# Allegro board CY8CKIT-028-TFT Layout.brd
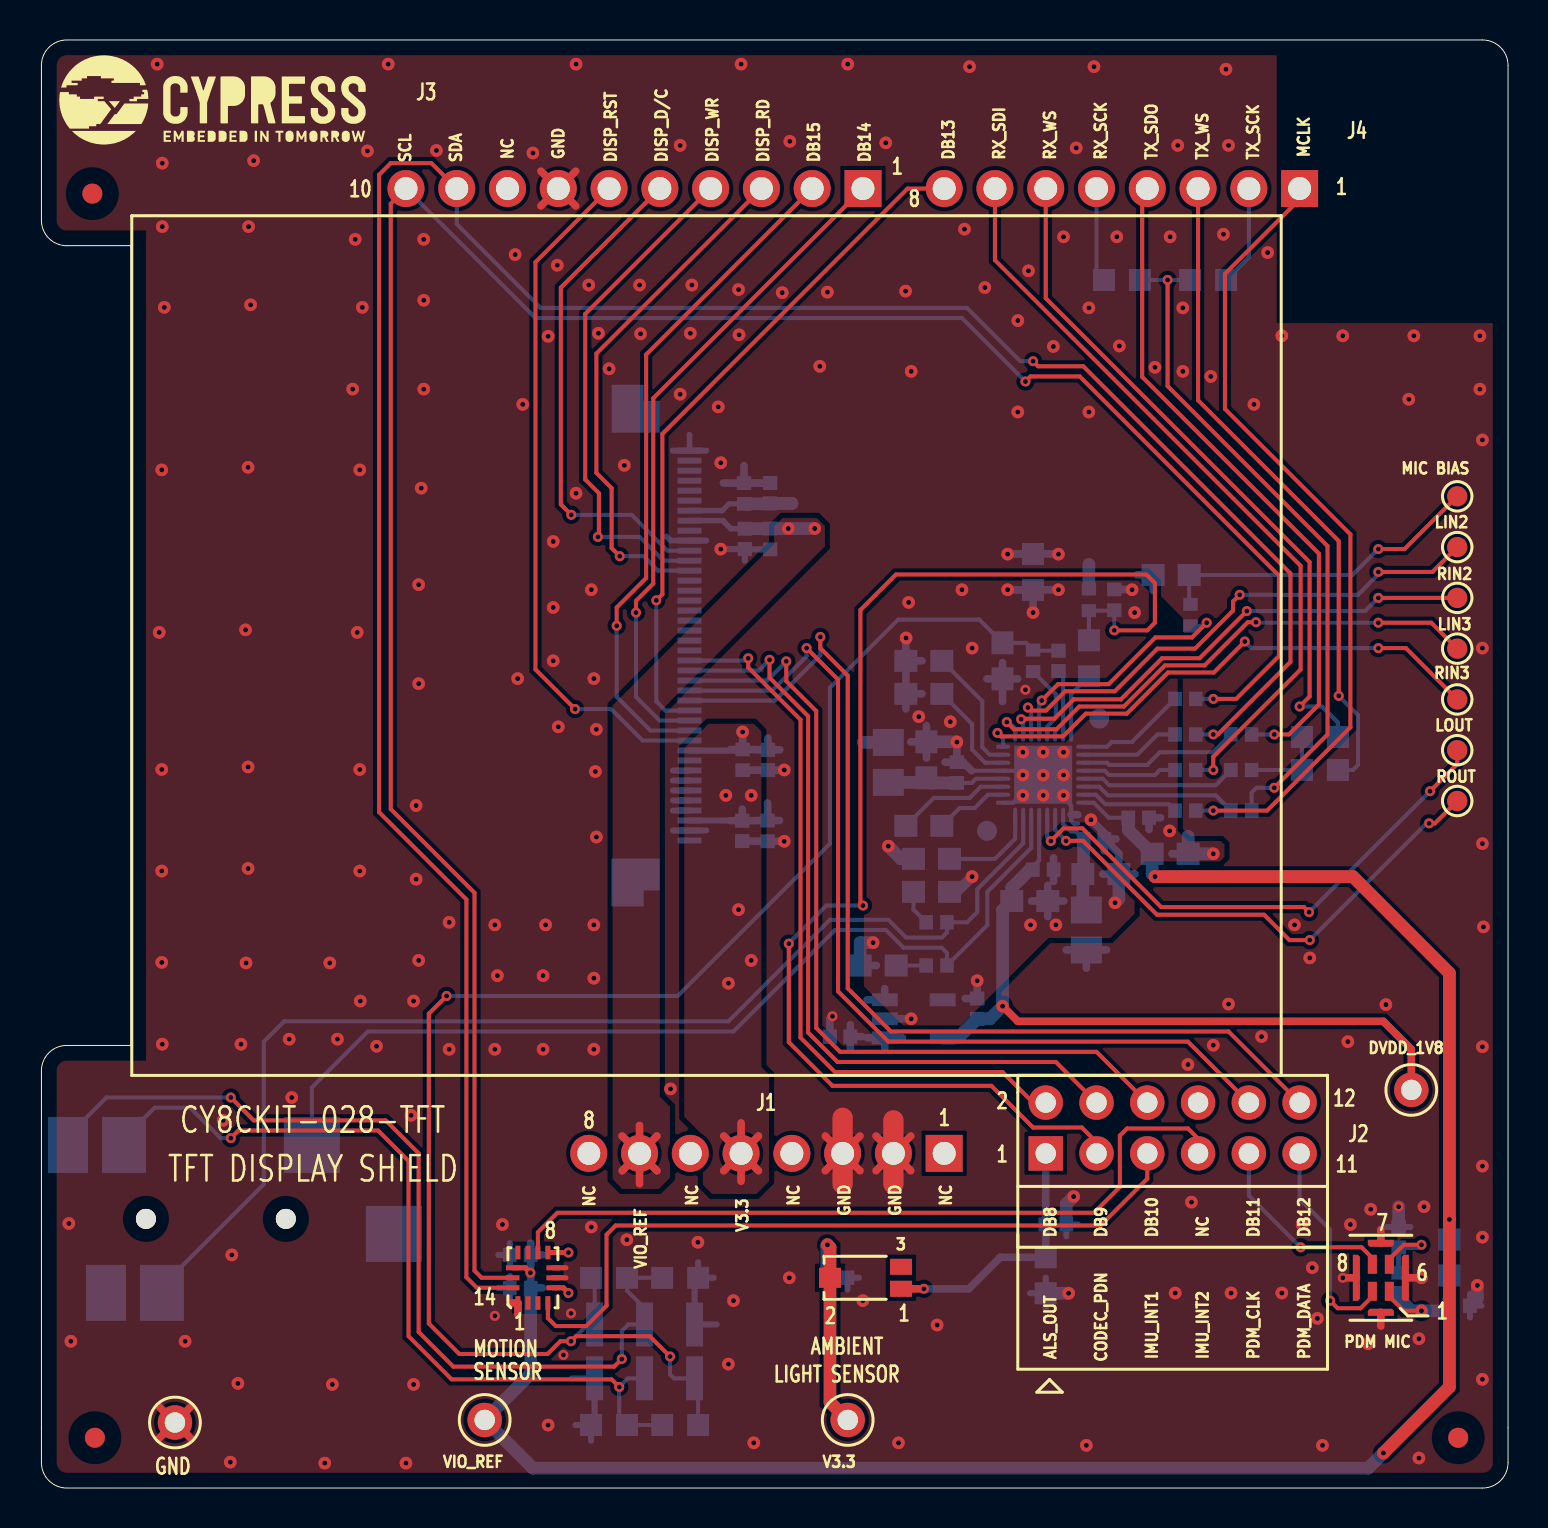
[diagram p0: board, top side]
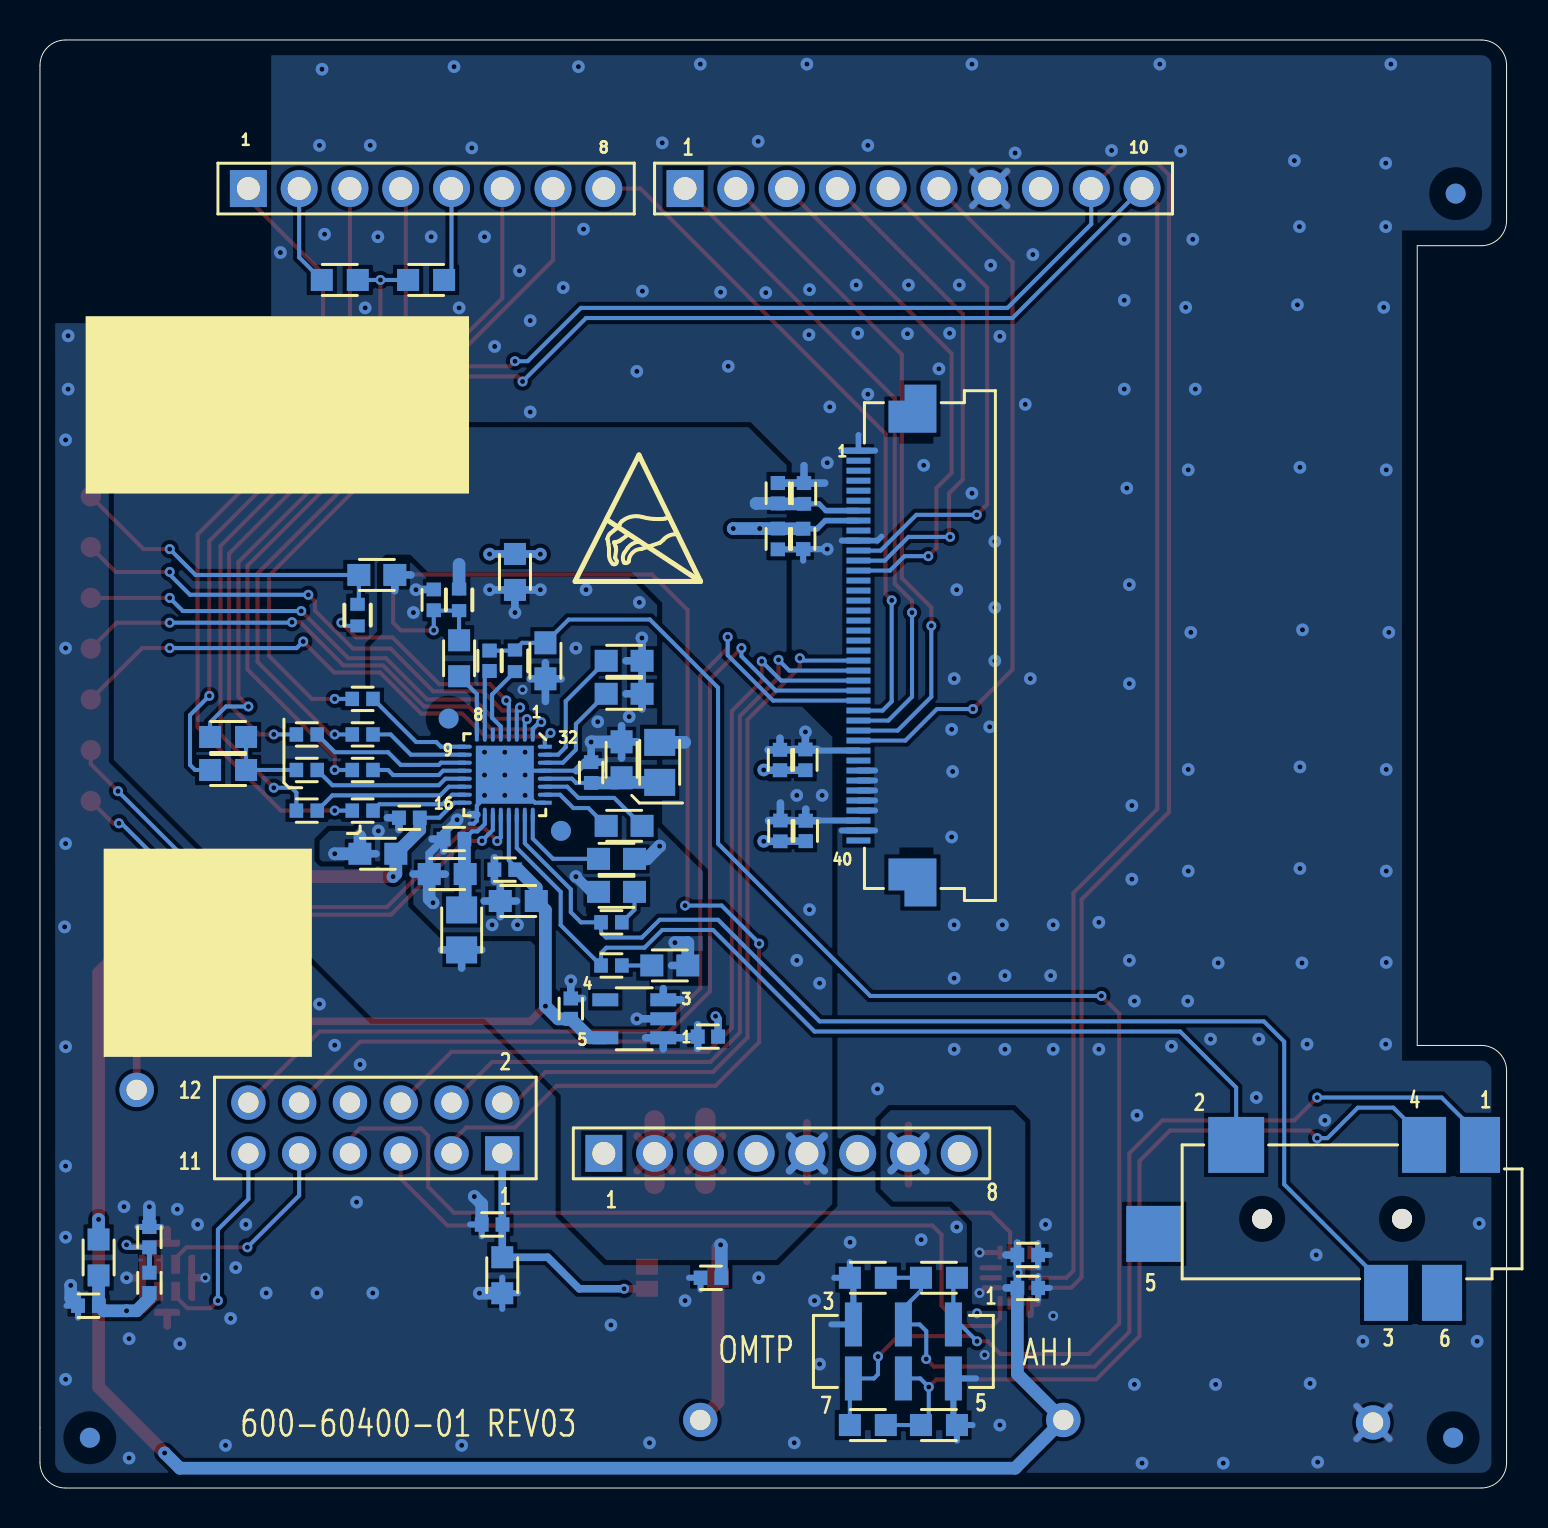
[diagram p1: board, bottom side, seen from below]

Outline 73.37 x 72.43 mm; copper layers: TOP, BOTTOM. Coordinates in mm from the lower left corner of the outline.
Outline path: 0,71.16 arc(0.37,72.06) 1.27,72.43 72.1,72.43 arc(73,72.06) 73.37,71.16 73.37,1.27 arc(73,0.37) 72.1,0 1.27,0 arc(0.37,0.37) 0,1.27 0,20.87 arc(0.37,21.77) 1.27,22.14 4.47,22.14 4.47,62.14 1.27,62.14 arc(0.37,62.51) 0,63.41 0,71.16

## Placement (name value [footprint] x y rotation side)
C1  1uF  [CAPC1005X55M_D]  36.46 49.76 90 bottom
C2  0.1uF  [CAPC1005X55M_C]  35.15 49.75 90 bottom
C3  0.1uF  [CAPC1005X55M_C]  36.46 47.47 270 bottom
C4  1uF  [CAPC1005X55M_D]  35.19 47.47 270 bottom
C5  0.001 uF  [CAPC1608X90M]  56.51 45.67 180 bottom
C6  0.1 uF  [CAPC1005X55M_C]  53.67 44.42 90 bottom
C7  1uF  [CAPC1005X55M_D]  50.88 41.38 270 bottom
C8  0.001 uF  [CAPC1608X90M]  48.08 41.38 270 bottom
C9  0.22uF  [CAPC1608X90M]  44.15 41.38 180 bottom
C10  0.22uF  [CAPC1608X90M]  44.15 39.73 180 bottom
C11  10uF  [CAPC1608X90M]  44.27 36.42 90 bottom
C12  0.1uF  [CAPC1005X55M_C]  35.08 36.42 270 bottom
C13  1uF  [CAPC1005X55M_D]  36.35 36.41 270 bottom
C14  0.1 uF  [CAPC1005X55M_C]  45.8 35.79 90 bottom
C15  0.1 uF  [CAPC1005X55M_C]  54.89 33.53 0 bottom
C16  2.2uF  [CAPC1608X90M]  44.15 33.12 0 bottom
C17  0.1uF  [CAPC1005X55M_C]  36.33 32.87 270 bottom
C18  1uF  [CAPC1005X55M_D]  35.06 32.87 270 bottom
C19  0.1 uF  [CAPC1005X55M_C]  52.65 32.46 0 bottom
C20  10uF  [CAPC1608X90M]  56.46 31.72 0 bottom
C21  2.2uF  [CAPC1608X90M]  44.53 31.47 180 bottom
C22  0.1 uF  [CAPC1005X55M_C]  50.11 30.93 0 bottom
C23  10uF  [CAPC1608X90M]  53 30.71 0 bottom
C24  0.22 uF  [CAPC1608X90M]  44.53 29.82 0 bottom
C25  10uF  [CAPC1608X90M]  49.44 29.36 0 bottom
C26  0.22 uF  [CAPC1608X90M]  41.86 26.14 180 bottom
C27  1uF  [CAPC1005X55M_D]  46.81 23.98 270 bottom
C28  1uF  [CAPC1005X55M_D]  39.95 22.58 0 bottom
C29  0.01 uF  [CAPC1005X55M_C]  50.75 13.18 0 bottom
C30  0.1 uF  [CAPC1005X55M_C]  23.95 11.66 180 bottom
C31  0.1uF  [CAPC1005X55M_C]  39.8 10.52 0 bottom
C32  0.1 uF  [CAPC1005X55M_C]  23.95 10.01 180 bottom
C33  0.1 uF  [CAPC1005X55M_C]  70.94 9.12 0 bottom
J1  CON8  [SULLINS_PBC08SAAN]  45.16 16.74 180 bottom
J2  CON 6x2  [SULLINS_PRPC006DAAN-RC_FLIP]  50.24 19.28 0 bottom
J3  CON10  [SULLINS_PBC10SAAN]  41.1 65 180 bottom
J4  CON8  [SULLINS_PBC08SAAN]  62.94 65 180 bottom
J5  0541324062  [MOLEX_541324062_CUSTOM]  32.42 51.89 90 bottom
J6  SJ-43516-SMT  [CUI_SJ-43516-SMT-TR]  1.33 17.16 90 bottom
L1  1K @ 100MHz  [INDC2012X105M]  42.37 36.3 270 bottom
L2  1K @ 100MHz  [INDC2012X105M]  52.27 27.91 90 bottom
NOREF  -  []  2.89 22.14 90 top
NOREF#2  -  [unnamed#2]  2.67 2.51 0 top
NOREF#3  -  []  -39.75 39.27 0 top
NOREF#4  -  [unnamed#2]  2.55 64.74 0 top
NOREF#5  -  []  116.66 74.14 0 top
NOREF#6  -  []  73.05 0.43 0 top
NOREF#7  -  []  -0.18 -12.98 0 top
NOREF#8  -  []  -295.07 -207.01 0 top
NOREF#9  -  []  8.46 69.44 0 top
NOREF#10  -  [unnamed#2]  70.87 2.51 0 top
NOREF#11  -  []  30.82 0 90 top
NOREF#12  -  []  0 68.68 0 top
NOREF#13  -  []  103.76 163.07 0 top
NOREF#14  -  []  43.39 51.96 180 bottom
NOREF#15  -  [unnamed#2]  2.55 64.74 180 bottom
NOREF#16  -  [unnamed#2]  2.67 2.51 180 bottom
NOREF#17  -  []  64.97 26.77 180 bottom
NOREF#18  -  []  43.66 48.16 180 bottom
NOREF#19  -  [unnamed#2]  70.87 2.51 180 bottom
NOREF#20  -  []  61.49 54.18 180 bottom
NOREF#21  -  []  -32.51 46.53 180 bottom
Q1  TEMT6000X01  [SENSOR_TEMT6000X01]  41.22 10.52 180 top
R1  0 OHM  [RESC1608X55M]  58.37 60.43 0 bottom
R2  0 OHM  [RESC1608X55M]  54.05 60.43 180 bottom
R3  0 OHM  [RESC1608X55M_A]  49.61 45.82 270 bottom
R4  10K  [RESC1005X40M]  52.4 44.42 90 bottom
R5  2.2K  [RESC1005X40M]  57.48 43.66 270 bottom
R6  0 OHM  [RESC1608X55M_A]  52.4 41.5 90 bottom
R7  2.2K  [RESC1005X40M]  49.61 41.38 270 bottom
R8  33OHM  [RESC1005X40M_B]  57.23 39.47 180 bottom
R9  33OHM  [RESC1005X40M_B]  60.02 37.69 180 bottom
R10  33OHM  [RESC1005X40M_B]  57.23 37.69 180 bottom
R11  0 OHM  [RESC1608X55M_A]  63.96 37.57 0 bottom
R12  0 OHM  [RESC1608X55M_A]  63.96 35.92 0 bottom
R13  33OHM  [RESC1005X40M_B]  60.02 35.92 180 bottom
R14  33OHM  [RESC1005X40M_B]  57.23 35.92 180 bottom
R15  33OHM  [RESC1005X40M_B]  60.02 33.88 180 bottom
R16  33OHM  [RESC1005X40M_B]  57.23 33.88 180 bottom
R17  33OHM  [RESC1005X40M_B]  44.78 28.3 0 bottom
R18  33OHM  [RESC1005X40M_B]  44.78 26.14 0 bottom
R19  10K  [RESC1005X40M_A]  67.89 12.55 90 bottom
R20  0 OHM  [RESC1608X55M_A]  70.43 11.53 90 bottom
R21  10K  [RESC1608X55M]  50.24 10.64 90 bottom
R22  0 OHM  [RESC1608X55M]  31.95 10.52 180 bottom
R23  0 OHM  [RESC1608X55M]  28.4 10.52 0 bottom
R24  10K  [RESC1005X40M_A]  67.89 10.26 90 bottom
R25  0 OHM  [RESC1608X55M]  31.95 3.15 180 bottom
R26  0 OHM  [RESC1608X55M]  28.4 3.15 0 bottom
SW1  JS202011JCQN  [SW_JS202011JCQN]  30.18 6.83 0 bottom
TP1  TP_SMD  [TP102C]  70.83 49.6 90 top
TP2  TP_SMD  [TP102C]  70.83 47.06 90 top
TP3  TP_SMD  [TP102C]  70.83 44.52 90 top
TP4  TP_SMD  [TP102C]  70.83 41.98 90 top
TP5  TP_SMD  [TP102C]  70.83 39.44 90 top
TP6  TP_SMD  [TP102C]  70.83 36.9 90 top
TP7  TP_SMD  [TP102C]  70.83 34.36 90 top
TP8  RED  [KEYSTONE_5000]  68.53 19.91 0 top
TP9  RED  [KEYSTONE_5000]  22.17 3.4 0 top
TP10  RED  [KEYSTONE_5000]  40.34 3.4 0 top
TP11  BLACK  [KEYSTONE_5000]  6.68 3.28 0 top
U1  BMI160  [BOSCH_BMI160]  24.59 10.52 90 top
U2  SPK0838HT4H-B  [KNOWLES_SPK0838HT4H-B]  67.01 10.52 0 top
U3  AK4954A  [QFN40P400X400X80-33N]  50.11 35.68 270 bottom
U4  TCR2EF18,LM(CT  [SOT95P275X140-5M]  43.64 23.47 0 bottom

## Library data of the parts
C1-C33 = CAPACITOR NON-POL
J1 J4 = CONN PCB 8
J2 = CONN PLUG 6x2
J3 = CONN PCB 10
J5 = E1260CS021_CONN_11
J6 = PJ-3755B-PA6T-TR_3
L1 L2 = INDUCTOR FERRITE
Q1 = PHOTO NPN_5
R1-R26 = RESISTOR
SW1 = SW_DPDT_JS202011CQN_1
TP1-TP11 = TEST_POINT
U1 = BMI160
U2 = SPK0838HT4H-B
U3 = AK4954A_0
U4 = AP22802_3

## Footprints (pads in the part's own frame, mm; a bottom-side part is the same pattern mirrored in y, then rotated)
BOSCH_BMI160
  rect 0.675x0.25 smd: 1(-1.262,0.75) 2(-1.262,0.25) 3(-1.262,-0.25) 4(-1.262,-0.75) 8(1.262,-0.75) 9(1.262,-0.25) 10(1.262,0.25) 11(1.262,0.75)
  rect 0.25x0.675 smd: 5(-0.5,-1.012) 6(0,-1.012) 7(0.5,-1.012) 12(0.5,1.012) 13(0,1.012) 14(-0.5,1.012)
CAPC1005X55M_C
  rect 0.69x0.72 smd: 1(-0.52,0) 2(0.52,0)
CAPC1005X55M_D
  rect 0.7x0.72 smd: 1(-0.51,0) 2(0.51,0)
CAPC1608X90M
  rect 1.15x1.1 smd: 1(-0.9,0) 2(0.9,0)
CUI_SJ-43516-SMT-TR
  round 1 hole 1.7 unplated: (-3.7,3.9) (-3.7,10.9)
  rect 2.8x2 smd: 1(0,0) 6(-7.4,1.9)
  rect 2.8x2.8 smd: 2(0,12.2) 5(-4.45,16.3)
  rect 2.8x2.2 smd: 3(-7.4,4.7) 4(0,2.8)
INDC2012X105M
  rect 1.35x1.55 smd: 1(-1,0) 2(1,0)
KEYSTONE_5000
  round 1.72 hole 1.02: 1(0,0)
KNOWLES_SPK0838HT4H-B
  rect 0.45x0.95 smd: 1(0.425,-0.675) 2(0.425,0.675) 3(-0.425,0.675) 4(-0.425,-0.675)
  custom 0.088x0.088 smd: 5(0,-1.725) 6(1.225,0) 7(0,1.725) 8(-1.225,0)
MOLEX_541324062_CUSTOM
  rect 0.3x1.2 smd: 1(0,0) 2(-0.5,0) 3(-1,0) 4(-1.5,0) 5(-2,0) 6(-2.5,0) 7(-3,0) 8(-3.5,0) 9(-4,0) 10(-4.5,0) 11(-5,0) 12(-5.5,0) 13(-6,0) 14(-6.5,0) 15(-7,0) 16(-7.5,0) 17(-8,0) 18(-8.5,0) 19(-9,0) 20(-9.5,0) 21(-10,0) 22(-10.5,0) 23(-11,0) 24(-11.5,0) 25(-12,0) 26(-12.5,0) 27(-13,0) 28(-13.5,0) 29(-14,0) 30(-14.5,0) 31(-15,0) 32(-15.5,0) 33(-16,0) 34(-16.5,0) 35(-17,0) 36(-17.5,0) 37(-18,0) 38(-18.5,0) 39(-19,0) 40(-19.5,0)
  custom 0.6x0.6 smd: SH1(-21.6,-2.7) SH2(2.1,-2.7)
QFN40P400X400X80-33N
  round 1 smd: (-2.809,-2.809) (2.809,2.809)
  custom 0.05x0.05 smd: 1(-1.999,1.4) 2(-1.999,1.001) 3(-1.999,0.599) 4(-1.999,0.201) 5(-1.999,-0.201) 6(-1.999,-0.599) 7(-1.999,-1.001) 8(-1.999,-1.4) 9(-1.4,-1.999) 10(-1.001,-1.999) 11(-0.599,-1.999) 12(-0.201,-1.999) 13(0.201,-1.999) 14(0.599,-1.999) 15(1.001,-1.999) 16(1.4,-1.999) 17(1.999,-1.4) 18(1.999,-1.001) 19(1.999,-0.599) 20(1.999,-0.201) 21(1.999,0.201) 22(1.999,0.599) 23(1.999,1.001) 24(1.999,1.4) 25(1.4,1.999) 26(1.001,1.999) 27(0.599,1.999) 28(0.201,1.999) 29(-0.201,1.999) 30(-0.599,1.999) 31(-1.001,1.999) 32(-1.4,1.999)
  rect 2.901x2.901 smd: 33(0,0)
RESC1005X40M
  rect 0.65x0.72 smd: 1(-0.54,0) 2(0.54,0)
RESC1005X40M_A
  rect 0.7x0.72 smd: 1(-0.51,0) 2(0.51,0)
RESC1005X40M_B
  rect 0.68x0.72 smd: 1(-0.52,0) 2(0.52,0)
RESC1608X55M
  rect 1.1x1.1 smd: 1(-0.9,0) 2(0.9,0)
RESC1608X55M_A
  rect 1.1x1.1 smd: 1(-0.9,0) 2(0.9,0)
SENSOR_TEMT6000X01
  rect 1.1x0.8 smd: 1(-1.775,0.55) 3(-1.775,-0.55)
  rect 1.1x1 smd: 2(1.775,0)
SOT95P275X140-5M
  rect 1.3x0.65 smd: 1(-1.45,0.95) 2(-1.45,0) 3(-1.45,-0.95) 4(1.45,-0.95) 5(1.45,0.95)
SULLINS_PBC08SAAN
  rect 1.85x1.85 hole 1.15: 1(0,0)
  round 1.85 hole 1.15: 2(2.54,0) 3(5.08,0) 4(7.62,0) 5(10.16,0) 6(12.7,0) 7(15.24,0) 8(17.78,0)
SULLINS_PBC10SAAN
  rect 1.85x1.85 hole 1.15: 1(0,0)
  round 1.85 hole 1.15: 2(2.54,0) 3(5.08,0) 4(7.62,0) 5(10.16,0) 6(12.7,0) 7(15.24,0) 8(17.78,0) 9(20.32,0) 10(22.86,0)
SULLINS_PRPC006DAAN-RC_FLIP
  rect 1.72x1.72 hole 1.02: 1(0,2.54)
  round 1.72 hole 1.02: 2(0,0) 3(2.54,2.54) 4(2.54,0) 5(5.08,2.54) 6(5.08,0) 7(7.62,2.54) 8(7.62,0) 9(10.16,2.54) 10(10.16,0) 11(12.7,2.54) 12(12.7,0)
SW_JS202011JCQN
  rect 0.85x2.2 smd: 1(-2.5,-1.35) 2(0,-1.35) 3(2.5,-1.35) 5(-2.5,1.35) 6(0,1.35) 7(2.5,1.35)
TP102C
  round 1.016 smd: 1(0,0)
unnamed#2
  round 1 smd: (0,0)

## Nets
AGND: C5.2 C6.2 C8.2 C9.2 C10.2 C11.2 C14.2 C15.2 C19.2 C20.2 C21.2 C22.2 C23.2 C24.2 C25.2 C26.2 C27.1 R3.2 U3.17(VSS3) U3.25(VSS2) U3.29(VSS1) U3.33(EPAD) U4.2(GND)
AVDD_3V3: C11.1 C14.1 L1.2 U3.28(AVDD)
DVDD_1V8: C22.1 C25.1 C27.2 TP8.1 U3.21(DVDD) U4.5(OUT)
GND_SIGNAL: C1.2 C2.2 C3.2 C4.2 C12.2 C13.2 C17.2 C18.2 C28.1 C29.2 C30.2 C31.2 C32.2 C33.2 J1.2 J1.3 J3.7 J5.1(GND#1) J5.10(CS) J5.33(GND#33) J5.34(LED-K1) J5.35(LED-K2) J5.36(LED-K3) J5.37(LED-K4) J5.39(GND#39) R3.1 R19.2 R21.1 R22.1 R26.1 SW1.3 SW1.5 TP11.1 U1.1(SDO) U1.6(GNDIO) U1.7(GND) U2.5(GND_1) U2.6(GND_2) U2.7(GND_3) U2.8(GND_4)
SVDD_3V3: C19.1 C23.1 L2.2 U3.18(SVDD)
VCC_3V3: C1.1 C2.1 C12.1 C13.1 C17.1 C18.1 C28.2 C31.1 J1.5 J5.7(VDD) J5.31(IMO) J5.38(LED-A) L1.1 L2.1 Q1.2(COLLECTOR) R4.2 TP10.1 U4.1(VIN) U4.3(CONTROL)
VCC_PDM: C33.1 R20.1 R24.1 U2.1(VDD)
ALS_OUT: C29.1 J2.1 Q1.1(EMITTER) R21.2
CODEC_LRCK: R11.1 R12.1 R13.1
CODEC_PDN_SW: C6.1 J2.3 R4.1 R6.2
HPL_OUT: J6.2(L) R18.2 U3.22(HPL)
HPR_OUT: J6.3(R) R17.2 U3.23(HPR)
I2C_SCL: J3.10 R8.1 U1.13(SCX)
I2C_SDA: J3.9 R10.1 U1.14(SDX)
I2S_BCLK: R1.1 R2.1 R15.1
I2S_MCLK: J4.1 R16.1
I2S_RX_SCK: J4.5 R2.2
I2S_RX_SDI: J4.7 R14.1
I2S_RX_WS: J4.6 R11.2
I2S_TX_SCK: J4.2 R1.2
I2S_TX_SDO: J4.4 R9.1
I2S_TX_WS: J4.3 R12.2
IMU_INT1: J2.5 U1.4(INT1)
IMU_INT2: J2.7 U1.9(INT2)
J6.1: J6.1(SLEEVE) R22.2 R23.2 SW1.2
J6.4: J6.4(MIC) R25.2 R26.2 SW1.6
LIN2: TP2.1 U3.3(LIN2)
LIN3: TP4.1 U3.1(LIN3)
LOUT: TP6.1 U3.20(SPP/LOUT)
MIC: C7.1 C8.1 R7.1 R23.1 R25.1 SW1.1 SW1.7
MIC_SEL: R19.1 R24.2 U2.2(SEL)
MPWR1: R7.2 U3.5(MPWR1)
MPWR2: R5.2 U3.4(MPWR2)
PDM_CLK: J2.9 U2.3(CLK)
PDM_DATA: J2.11 U2.4(DATA)
RIN2: TP3.1 U3.2(RIN2)
RIN3: TP5.1 U3.32(RIN3)
ROUT: TP7.1 U3.19(SPN/ROUT)
TFT_DISP_D/C: J3.5 J5.11(D/C)
TFT_DISP_DB8: J2.2 J5.22(DB8)
TFT_DISP_DB9: J2.4 J5.23(DB9)
TFT_DISP_DB10: J2.6 J5.24(DB10)
TFT_DISP_DB11: J2.10 J5.25(DB11)
TFT_DISP_DB12: J2.12 J5.26(DB12)
TFT_DISP_DB13: J4.8 J5.27(DB13)
TFT_DISP_DB14: J3.1 J5.28(DB14)
TFT_DISP_DB15: J3.2 J5.29(DB15)
TFT_DISP_RD_L: J3.3 J5.13(RD)
TFT_DISP_RST_L: J3.6 J5.30(RESET)
TFT_DISP_WR_L: J3.4 J5.12(WR)
VIO_REF: C3.1 C4.1 C15.1 C20.1 C30.1 C32.1 J1.7 J5.8(IOVDD) R20.2 TP9.1 U1.5(VDDIO) U1.8(VDD) U1.12(CSB) U3.16(TVDD)
N17262592: R8.2 U3.9(SCL)
N17262616: R10.2 U3.10(SDA)
N17313413: C7.2 U3.7(LIN1/DMDAT)
N17337588: R6.1 U3.8(PDN)
N17337626: R16.2 U3.15(MCKI)
N17337628: R15.2 U3.14(BICK)
N17337654: R9.2 U3.11(SDTI)
N17337656: R14.2 U3.12(SDTO)
N17337674: R13.2 U3.13(LRCK)
N17337833: C16.2 U3.26(CP)
N17337835: C16.1 U3.27(CN)
N17337935: C10.1 U3.30(VCOM)
N17337954: C9.1 U3.31(MRF)
N17338534: C21.1 U3.24(VEE)
N17339065: C24.1 R17.1
N17348097: C5.1 R5.1 TP1.1
N173390790: C26.1 R18.1

Pads without a net: J1 1 4 6 8; J2 8; J3 8; J5 2 3 4 5 6 9 14 15 16 17 18 19 20 21 32 40 SH1 SH2; J6 5 6; Q1 3; U1 2 3 10 11; U3 6; U4 4

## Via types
v1: diameter 0.635, hole 0.254, TOP to BOTTOM, 238 vias
v2: diameter 0.5, hole 0.25, TOP to BOTTOM, 68 vias

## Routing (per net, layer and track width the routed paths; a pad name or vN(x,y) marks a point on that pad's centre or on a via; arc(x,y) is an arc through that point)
AGND: length 51.6
  BOTTOM w0.203: v1(49.1,35.66) 48.88,35.88 U3.29 46.53,35.88 ; v1(49.1,34.65) 48.97,34.65 48.61,34.28 U3.25 ; 51.87,33.23 51.66,33.23 51.51,33.37 U3.17 51.51,34.14 51.4,34.25 51.4,34.38 v1(51.13,34.65)
  BOTTOM w0.381: 56.56,31.72 C20.2 ; C10.2 43.25,40.51 ; C10.2 44.05,39.73 ; C10.2 43.25,38.97 ; 53.17,31.87 C19.2 ; C19.2 53.75,32.46 ; C19.2 53.9,31.74 C23.2 ; C19.2 53.17,32.75 v1(52.5,33.43) ; 54.81,45.67 C5.2 55.61,44.89 ; v1(46.81,25.37) C27.1 46.22,24.49 ; C9.2 43.25,42.53 v1(43.26,42.52) ; C9.2 44.05,41.38 ; C9.2 43.25,40.59 ; 46.53,35.88 46.1,36.31 C14.2 ; C25.2 51.15,29.36 ; C25.2 50.34,28.58 ; C25.2 50.34,30.14 ; C25.2 49.53,29.36 ; 48.08,39.34 C8.2 ; C8.2 47.3,40.48 ; C8.2 48.83,40.48 ; C8.2 48.08,41.28 ; R3.2 v1(49.61,43.79) ; R3.2 50.87,44.92 v1(50.88,44.93) ; R3.2 48.35,44.92 v1(48.34,44.93) ; 45.2,36.31 C14.2 ; C14.2 v1(45.8,37.31) ; U4.2 v1(43.51,23.47) ; C6.2 54.55,44.94 v1(54.56,44.93) ; 55.99,33.53 C15.2 55.41,32.94 ; 50.63,30.34 C22.2 50.63,31.52 ; 53.09,30.71 C23.2 ; C23.2 54.7,30.71 ; U3.17 51.84,33.68 ; 44.27,36.52 C11.2 ; C11.2 44.27,38.13 ; C11.2 43.49,37.32 ; C26.2 41.77,26.14
  BOTTOM w0.508: C24.2 45.8,29.82 v1(46.56,30.58)
  BOTTOM w0.635: C26.2 40.96,27.27 40.97,27.28 v1(41.61,27.28) ; C21.2 43,31.47 v1(42.37,32.11) ; v1(58.62,31.72) C20.2 57.36,32.6 ; v1(53.71,29.28) 53.9,29.47 C23.2 ; v1(45.8,37.31) 45.79,37.32 C11.2
  vias: v1(43.38,44.3) v1(43.89,38.58) v1(45.47,38.33) v1(46.05,44.93) v1(46.56,42.01) v1(49.1,36.8) v1(49.48,28.17) v1(50.11,36.8) v1(50.11,35.66) v1(50.11,34.65) v1(50.75,28.17) v1(51.13,36.8) v1(51.13,35.66) v1(54.69,43.79) v1(56.44,32.87) v2(49.23,39.93)
AVDD_3V3: length 6
  BOTTOM w0.203: U3.28 46.76,35.48 46.55,35.27 C14.1
  BOTTOM w0.635: L1.2 44.05,35.3 C11.1 44.53,35.27 C14.1
DVDD_1V8: length 37.4
  TOP w0.381: v1(48.08,24.1) 48.08,24.1 48.84,23.34 67.13,23.34 68.53,21.95 TP8.1
  BOTTOM w0.203: C22.1 49.59,31.08 49.91,31.4 U3.21
  BOTTOM w0.635: C22.1 49.45,30.93 48.54,30.02 C25.1 48.08,28.9 v1(48.08,24.1) 47.45,23.47 C27.2 45.86,22.52 U4.5
GND_SIGNAL: length 91.1
  TOP w0.254: 26.24,10.52 U1.6 ; 26.24,11.02 U1.7
  TOP w0.381: 24.99,65.87 25.86,65 ; 25.86,65 26.73,65.87 ; 25.86,65 24.99,64.13 ; 25.86,65 26.73,64.13 ; J1.3 40.95,15.87 ; J1.3 39.21,15.87 ; J1.3 39.21,17.61 ; J1.3 40.95,17.61 ; U2.7 67.01,12.93 ; U2.6 v1(69.04,10.52) ; J1.2 43.49,15.87 ; J1.2 41.75,17.61 ; J1.2 43.49,17.61 ; J1.2 41.75,15.87 ; 23.84,8.68 U1.1 23.48,9.25 ; 5.86,4.1 TP11.1 ; TP11.1 7.5,4.1 ; TP11.1 5.86,2.45 ; TP11.1 7.5,2.45 ; U2.5 67.01,8.1 ; U2.8 v2(65.1,10.52)
  TOP w1.016: 40.08,18.52 J1.3 40.08,15.21 ; 42.62,18.39 J1.2 42.62,15.21
  BOTTOM w0.279: J5.10 31.48,47.39 31.27,47.6 ; 32.41,52.68 32.42,52.67 J5.1
  BOTTOM w0.305: 27.5,2.37 R26.1 ; R26.1 26.72,3.15 ; R26.1 27.68,3.33 SW1.5 26.54,5.48 ; 68.49,13.06 R19.2 67.3,13.06 ; 31.59,34.39 J5.36 ; 49.46,9.74 R21.1 ; R21.1 50.24,10.52 ; R21.1 50.24,8.96 ; 71.46,8.53 C33.2 ; C33.2 71.46,9.71 ; C33.2 72.04,9.12 ; 40.9,10.52 C31.2 40.32,9.92 ; C3.2 35.2,46.95 C4.2 ; R22.1 32.85,11.3 ; R22.1 33.63,10.52 ; R22.1 32.68,10.34 SW1.3 33.78,8.18 ; 23.43,9.42 C32.2 ; C32.2 22.86,10.01 ; C32.2 23.43,10.6 ; 31.59,35.89 J5.33 ; 31.59,51.89 J5.1 33.26,51.89 ; 25.86,65 26.73,64.13 ; 25.86,65 24.99,64.13 ; 25.86,65 24.99,65.87 ; 25.86,65 26.73,65.87 ; 5.86,4.1 TP11.1 ; TP11.1 5.86,2.45 ; TP11.1 7.5,2.45 ; TP11.1 7.5,4.1 ; J5.10 33.26,47.39 ; 31.59,33.89 J5.37 ; 31.59,32.89 J5.39 33.26,32.89 ; 22.86,11.66 C30.2 ; C30.2 23.43,11.07 ; C30.2 23.43,12.25 ; 51.85,13.18 C29.2 51.27,12.59 ; 31.59,34.89 J5.35 ; 31.59,35.39 J5.34 ; v1(33.99,46.96) 33.99,46.96 C4.2 ; C4.2 35.19,46.38
  BOTTOM w0.381: C2.2 35.15,51.14 ; C2.2 34.11,50.27 ; C2.2 C1.2 ; v1(37.16,35.92) 37.15,35.9 C13.2 C12.2 ; C28.1 39.44,23.47 v2(39.57,23.6) ; v1(50.88,46.71) 50.87,46.72 R3.1 48.35,46.72 v1(48.34,46.71) ; v1(37.16,32.35) C17.2 36.32,32.36 C18.2
  BOTTOM w0.635: R21.1 v1(51.38,9.74) ; C29.2 51.27,14.21 v1(51.64,14.58) ; v1(71.83,10.13) 71.83,9.49 C33.2 ; R19.2 v2(67.89,14.07)
  vias: v1(1.37,13.23) v1(1.47,7.34) v1(5.79,71.22) v1(5.89,42.8) v1(6.02,50.93) v1(6.02,35.94) v1(6.02,30.86) v1(6.02,26.29) v1(6.05,66.27) v1(6.05,63.09) v1(6.05,22.2) v1(6.15,59.05) v1(7.19,7.34) v1(9.09,18.39) v1(9.53,11.66) v1(9.45,1.3) v1(9.83,5.23) v1(9.98,22.2) v1(10.21,42.93) v1(10.24,26.26) v1(10.36,63.09) v1(10.34,51.05) v1(10.34,36.07) v1(10.34,30.99) v1(10.46,59.18) v1(10.62,66.4) v1(12.4,22.45) v1(12.52,19.53) v1(14.17,1.24) v1(14.43,26.26) v1(14.55,5.18) v1(14.81,22.45) v1(15.57,54.97) v1(15.7,62.46) v1(15.8,42.8) v1(15.93,50.93) v1(15.93,35.94) v1(15.93,30.86) v1(15.95,24.36) v1(16.05,59.05) v1(16.31,66.88) v1(16.76,22.1) v1(17.35,71.22) v1(18.24,1.24) v1(18.49,18.64) v1(18.62,24.36) v1(18.62,5.18) v1(18.75,34.14) v1(18.75,30.45) v1(18.87,45.19) v1(18.87,40.23) v1(18.87,26.39) v1(19,50.01) v1(19.13,62.46) v1(19.13,59.41) v1(19.13,54.97) v1(19.76,66.9) v1(20.4,28.3) v1(20.4,21.95) v1(22.68,28.17) v1(22.68,21.95) v1(22.81,25.63) v1(23.06,13.18) v1(23.7,61.7) v1(23.83,40.49) v1(24.08,54.2) v1(24.59,66.78) v1(25.1,25.63) v1(25.1,21.95) v1(25.22,28.17) v1(25.35,57.61) v1(25.35,3.15) v1(25.6,47.35) v1(25.6,44.04) v1(25.6,41.38) v1(25.81,61.16) v1(25.86,38.07) v1(26.75,71.22) v1(26.75,49.76) v1(27.38,60.17) v1(27.51,44.93) v1(27.51,13.06) v1(27.64,40.49) v1(27.71,35.84) v1(27.64,28.17) v1(27.64,25.5) v1(27.64,21.95) v1(27.76,37.95) v1(27.76,32.56) v1(27.86,57.76) v1(28.4,55.98) v1(29.16,51.16) v1(29.29,12.42) v1(29.92,60.17) v1(29.97,57.73) v1(31.47,19.96) v1(31.95,67.16) v1(31.95,54.71) v1(32.46,57.76) v1(32.54,60.17) v1(32.84,12.29) v1(33.86,54.08) v1(33.99,51.28) v1(34.37,6.2) v1(34.62,9.37) v1(34.87,59.94) v1(34.9,57.68) v1(35,71.22) v1(35.64,2.26) v1(37.06,59.79) v1(37.41,10.52) v1(37.44,67.36) v1(38.94,56.11) v1(39.32,59.82) v1(40.34,71.22) v1(41.1,9.37) v1(42.24,67.28) v1(42.88,2.26) v1(43.23,59.87) v1(43.51,55.85) v1(44.81,8.15) v1(46.18,62.97) v1(46.43,71.09) v1(47.19,60.05) v1(48.84,58.39) v1(48.84,53.82) v1(49.38,60.88) v1(50.62,57.1) v1(51.13,62.59) v1(51.77,67.03) v1(52.27,2.13) v1(52.4,59.03) v1(52.4,53.82) v1(52.65,71.09) v1(53.8,62.59) v1(53.92,57.12) v1(55.7,56.06) v1(56.46,62.59) v1(56.72,9.75) v1(56.85,67.16) v1(57.1,59.03) v1(57.1,55.85) v1(57.35,21.18) v1(57.53,14.3) v1(58.5,55.6) v1(58.62,22.15) v1(59.13,62.71) v1(59.26,70.97) v1(59.39,67.16) v1(59.39,24.21) v1(59.51,9.75) v1(60.66,54.2) v1(61.04,22.58) v1(61.34,61.8) v1(62.05,57.63) v1(62.05,9.75) v1(62.69,28.17) v1(63.07,13.18) v1(63.45,26.52) v1(63.58,11.02) v1(63.83,8.48) v1(64.08,2.13) v1(65.1,57.63) v1(65.35,22.33) v1(65.48,13.18) v1(66.37,7.21) v1(66.5,13.94) v1(67.26,24.18) v1(68.4,54.46) v1(68.66,57.63) v1(68.91,7.47) v1(68.91,1.5) v1(69.16,14.07) v1(71.96,57.63) v1(71.96,54.97) v1(72.09,52.43) v1(72.09,42.01) v1(72.09,32.23) v1(72.09,22.07) v1(72.09,16.1) v1(72.09,12.55) v1(72.09,5.44) v1(72.14,28.07) v2(22.68,8.61) v2(26.11,6.65) v2(26.49,8.74)
SVDD_3V3: length 5.4
  BOTTOM w0.203: U3.18 51.11,33.21 51.49,32.84 51.75,32.84 C19.1
  BOTTOM w0.635: L2.2 52.1,29.09 C23.1 52.13,30.75 C19.1
VCC_3V3: length 51.9
  TOP w0.381: 34.13,15.87 35,16.74 ; 35,16.74 34.13,17.61 ; 35,16.74 35.87,17.61 ; 35,16.74 35.87,15.87 ; 35,16.74 35,18.26 ; 35,16.74 35,15.34
  TOP w0.635: TP10.1 39.45,4.29 Q1.2 39.45,12.04 v1(39.32,12.17)
  BOTTOM w0.254: C2.1 34.39,49.23 34.06,48.89
  BOTTOM w0.279: 34.06,48.89 J5.7
  BOTTOM w0.305: J5.38 34.46,33.39 34.47,33.38 ; C12.1 35.02,36.89 J5.31
  BOTTOM w0.381: 41.31,24.42 U4.3 42.19,24.98 ; C17.1 36.92,33.39 ; C17.1 36.33,34.26 ; C17.1 35.74,33.39 ; 52.27,26.01 L2.1 ; L2.1 51.27,26.91 ; L2.1 53.28,26.91 ; 34.13,15.87 35,16.74 ; 35,16.74 35.87,15.87 ; 35,16.74 35.87,17.61 ; 35,16.74 34.13,17.61 ; 34.47,33.38 C18.1 ; C18.1 35.06,33.96 ; C18.1 35.65,33.38 ; C12.1 35.08,37.52 ; C12.1 35.67,36.94 ; C12.1 34.49,36.94 ; 35.76,36.92 C13.1 ; C13.1 36.94,36.92 ; C13.1 36.35,37.51 ; 42.19,21.96 U4.1 ; U4.1 43.07,22.52 ; U4.1 41.31,22.52 ; C28.2 40.46,23.17 ; C28.2 41.05,22.58 ; C28.2 40.46,21.99
  BOTTOM w0.635: 37.54,49.25 37.54,49.25 C1.1 36.44,49.23 C2.1 ; L1.1 41.11,37.3 ; v1(39.32,12.17) 39.28,12.13 C31.1 ; R4.2 52.4,46.2
  vias: v1(34.24,34.65) v1(34.37,25.25) v1(34.87,28.93) v1(35.08,37.82) v1(35.51,34.65) v1(35.51,26.39)
VCC_PDM: length 6.8
  TOP w0.203: v1(69.04,8.86) 68.15,8.86 67.43,9.58 U2.1
  BOTTOM w0.635: R20.1 70.43,9.13 C33.1 70.17,8.86 v1(69.04,8.86) 68.53,8.86 67.89,9.5 R24.1
ALS_OUT: length 13.1
  TOP w0.381: Q1.1 v2(44.15,9.97)
  BOTTOM w0.381: J2.1 50.24,13.19 C29.1 50.24,13.17 R21.2 47.97,11.54 46.39,9.97 v2(44.15,9.97)
CODEC_LRCK: length 4.2
  BOTTOM w0.203: R11.1 R12.1 R13.1
CODEC_PDN_SW: length 65.9
  TOP w0.203: v2(41.1,29.13) 40.97,29.26 40.97,43.92 42.75,45.69 55.27,45.69 55.7,45.26 55.7,43.28 55.32,42.9 v2(53.67,42.9) ; J2.3 52.78,17.3 52.04,18.03 49.61,18.03 47.52,20.12 39.57,20.12 37.39,22.3 v2(37.39,27.23)
  BOTTOM w0.203: R6.2 R4.1 53.65,43.88 C6.1 v2(53.67,42.9) ; v2(41.1,29.13) 39.27,29.13 37.39,27.25 v2(37.39,27.23)
HPL_OUT: length 48.3
  BOTTOM w0.203: J6.2 13.53,20.03 16.33,22.83 34.62,22.83 39.7,27.91 42.24,27.91 43.13,27.03 45.03,27.03 45.3,26.76 R18.2 47.32,28.16 47.32,29.82 49.51,32.01 U3.22
HPR_OUT: length 59.9
  BOTTOM w0.203: U3.23 49.11,32.25 46.81,29.95 46.81,28.8 46.3,28.3 R17.2 45.3,27.79 45.05,27.53 43.26,27.53 42.37,28.42 39.45,28.42 34.37,23.34 12.14,23.34 11.13,22.33 11.13,15.19 6.03,10.09 J6.3
I2C_SCL: length 119.2
  TOP w0.203: v2(49.23,55.35) 49.48,55.6 51.94,55.6 61.91,45.64 61.91,41.61 59.77,39.47 v2(58.62,39.47) ; J3.10 17.48,64.24 17.48,33.96 21.67,29.77 21.67,10.87 22.02,10.52 U1.13
  BOTTOM w0.203: v2(49.23,55.35) 46.05,58.52 24.71,58.52 J3.10 ; R8.1 v2(58.62,39.47)
I2C_SDA: length 125.5
  TOP w0.203: U1.14 21.79,10.02 21.26,10.54 21.26,29.44 16.89,33.81 16.89,65.68 17.48,66.27 19.51,66.27 20.78,65 ; v2(58.62,37.69) 58.85,37.69 62.48,41.33 62.48,45.75 52.12,56.11 49.86,56.11 v2(49.61,56.36)
  BOTTOM w0.203: 20.78,65 20.78,63.22 24.97,59.03 46.3,59.03 48.97,56.36 v2(49.61,56.36) ; R10.1 v2(58.62,37.69)
I2S_BCLK: length 34.5
  TOP w0.203: v2(56.34,60.43) 56.34,55.12 64.34,47.12 64.34,37.69 v2(61.67,35.03)
  BOTTOM w0.203: R2.1 v2(56.34,60.43) R1.1 ; v2(61.67,35.03) 60.78,35.03 60.54,34.78 R15.1
I2S_MCLK: length 40.6
  TOP w0.203: v2(58.62,33.88) 61.32,33.88 65.48,38.05 65.48,47.7 59.21,53.97 59.21,60.73 62.94,64.47 J4.1
  BOTTOM w0.203: R16.1 v2(58.62,33.88)
I2S_RX_SCK: length 4.7
  BOTTOM w0.203: R2.2 52.78,60.8 J4.5
I2S_RX_SDI: length 38.1
  TOP w0.203: J4.7 47.7,61.42 62.99,46.13 62.99,40.94 58.62,36.58 v2(58.62,35.92)
  BOTTOM w0.203: R14.1 v2(58.62,35.92)
I2S_RX_WS: length 34.6
  TOP w0.203: v2(62.94,39.09) 63.44,39.59 63.44,46.31 50.24,59.51 J4.6
  BOTTOM w0.203: v2(62.94,39.09) 64.06,39.09 64.86,38.29 R11.2
I2S_TX_SCK: length 5
  BOTTOM w0.203: R1.2 60.4,61.56 J4.2
I2S_TX_SDO: length 33.6
  TOP w0.203: J4.4 55.07,64.74 55.07,55.58 63.91,46.74 63.91,39.19 62.41,37.69 v2(61.67,37.69)
  BOTTOM w0.203: R9.1 v2(61.67,37.69)
I2S_TX_WS: length 33.3
  TOP w0.203: v2(64.9,39.62) 64.9,47.37 57.86,54.41 J4.3
  BOTTOM w0.203: v2(64.9,39.62) 65.86,38.66 65.86,36.17 65.61,35.92 R12.2
IMU_INT1: length 37.3
  TOP w0.203: J2.5 55.32,15.47 52.98,13.13 28.73,13.13 28.27,12.67 28.27,9.12 27.25,8.1 25.73,8.1 25.34,8.5 U1.4
IMU_INT2: length 38.6
  TOP w0.203: U1.9 24.84,12.8 25.81,13.77 52.65,13.77 53.95,15.06 53.95,17.63 54.31,17.98 57.35,17.98 57.86,17.48 J2.7
J6.1: length 47
  TOP w0.203: v2(9.47,19.53) 10.62,18.39 17.22,18.39 18.87,16.74 18.87,7.81 20.61,6.07 28.65,6.07 v2(29.03,6.45)
  BOTTOM w0.203: J6.1 1.33,17.61 3.25,19.53 v2(9.47,19.53) ; R22.2 R23.2 29.3,9.87 30.18,8.99 SW1.2 29.37,8.18 29.03,7.85 v2(29.03,6.45)
J6.4: length 42.2
  TOP w0.203: v2(28.91,5.05) 28.52,5.44 20.52,5.44 18.36,7.59 18.36,16.36 16.84,17.88 9.86,17.88 v2(9.47,17.5)
  BOTTOM w0.203: SW1.6 29.33,5.48 v2(28.91,5.05) 28.91,3.54 R26.2 R25.2 ; J6.4 4.13,17.49 5.66,19.02 7.44,19.02 8.97,17.5 v2(9.47,17.5)
LIN2: length 26.7
  TOP w0.203: v2(66.88,45.82) 69.58,45.82 TP2.1 ; v2(59.94,44.68) 59.61,44.35 59.61,43.89 57.71,41.99 55.83,41.99 53.7,39.85 51.21,39.85 50.25,38.89 49.5,38.89 v2(49.35,39.04)
  BOTTOM w0.203: v2(59.94,44.68) 65.86,44.68 66.88,45.69 v2(66.88,45.82) ; U3.3 49.51,38.88 v2(49.35,39.04)
LIN3: length 26.3
  TOP w0.203: v2(60.76,43.31) 60.35,43.31 58.19,41.15 56.21,41.15 54.15,39.09 51.92,39.09 50.78,37.95 48.65,37.95 v2(48.29,38.31) ; v2(66.88,43.28) 69.53,43.28 TP4.1
  BOTTOM w0.203: U3.1 48.71,37.98 48.38,38.31 v2(48.29,38.31) ; v2(60.76,43.31) 60.78,43.28 v2(66.88,43.28)
LOUT: length 27.5
  TOP w0.203: v2(50.5,32.36) 51.13,32.99 52.08,32.99 56.02,29.06 63.16,29.06 v2(63.42,28.8) ; TP6.1 70.83,36.21 v2(69.46,34.85)
  BOTTOM w0.203: v2(63.42,28.8) v2(69.46,34.85) ; v2(50.5,32.36) 50.31,32.54 U3.20
MIC: length 82.4
  TOP w0.203: v2(20.27,24.61) 19.38,23.72 19.38,8.23 20.9,6.71 25.32,6.71 25.96,7.34 v2(26.49,7.34) 26.75,7.59 30.43,7.59 v2(31.45,6.58)
  BOTTOM w0.203: C7.1 49.64,41.89 R7.1 49.25,42.28 C8.1 46.92,43.44 42.85,43.44 39.45,40.03 39.45,32.23 31.83,24.61 v2(20.27,24.61) ; 32.85,3.15 32.85,5.3 SW1.7 31.65,5.48 31.45,5.69 v2(31.45,6.58) ; v2(26.49,7.34) 27.33,8.18 SW1.1 27.68,10.34 R23.1
MIC_SEL: length 4.6
  TOP w0.203: v2(69.04,12.17) 68.15,12.17 67.43,11.45 U2.2
  BOTTOM w0.254: R24.2 R19.1 68.91,12.04 v2(69.04,12.17)
MPWR1: length 3.8
  BOTTOM w0.203: R7.2 50.75,39.69 50.75,38.52 50.31,38.09 U3.5
MPWR2: length 12.5
  TOP w0.203: v2(58.29,43.28) 57.55,42.54 55.73,42.54 53.39,40.21 50.85,40.21 v2(50.04,39.39)
  BOTTOM w0.203: v2(50.04,39.39) 50.04,39.34 49.91,39.22 U3.4 ; R5.2 58.13,43.12 v2(58.29,43.28)
PDM_CLK: length 9.9
  TOP w0.203: v2(62.99,12.04) 66.04,12.04 66.58,11.5 U2.3
  BOTTOM w0.203: J2.9 60.4,14.63 v2(62.99,12.04)
PDM_DATA: length 10.8
  TOP w0.203: U2.4 66.58,9.58 65.99,8.99 64.85,8.99 v2(64.47,9.37)
  BOTTOM w0.203: J2.11 62.94,14.45 64.47,12.93 v2(64.47,9.37)
RIN2: length 25.1
  TOP w0.203: v2(60.3,43.87) 57.94,41.5 56.06,41.5 54,39.45 51.64,39.45 50.67,38.48 49.04,38.48 v2(49.01,38.46) ; v2(66.88,44.52) TP3.1
  BOTTOM w0.203: v2(60.3,43.87) 66.22,43.87 v2(66.88,44.52) ; v2(49.01,38.46) 49.11,38.35 U3.2
RIN3: length 27
  TOP w0.203: v2(60.2,42.34) 58.65,40.79 56.35,40.79 54.3,38.73 52.25,38.73 51.11,37.6 48,37.6 v2(47.83,37.77) ; TP5.1 68.26,42.01 v2(66.88,42.01)
  BOTTOM w0.203: v2(47.83,37.77) 48.12,37.48 U3.32 ; v2(66.88,42.01) 60.53,42.01 v2(60.2,42.34)
ROUT: length 26
  TOP w0.203: TP7.1 69.71,33.25 v2(69.42,33.25) ; v2(63.45,27.41) 62.43,27.41 61.16,28.68 55.8,28.68 52.11,32.37 v2(51.26,32.37)
  BOTTOM w0.203: U3.19 50.71,32.92 v2(51.26,32.37) ; v2(69.42,33.25) 69.29,33.25 v2(63.45,27.41)
TFT_DISP_D/C: length 25.2
  TOP w0.203: J3.5 25.98,60.05 25.98,49.2 v2(26.5,48.68)
  BOTTOM w0.203: v2(26.5,48.68) 29.53,48.68 31.32,46.89 J5.11
TFT_DISP_DB8: length 36.7
  TOP w0.203: v2(35.36,41.5) 35.36,41.05 37.97,38.43 37.97,22.53 39.7,20.8 48.08,20.8 49.61,19.28 J2.2
  BOTTOM w0.203: v2(35.36,41.5) 35.24,41.39 J5.22
TFT_DISP_DB9: length 39.5
  TOP w0.203: J2.4 50.75,21.31 39.83,21.31 38.35,22.78 38.35,38.61 36.42,40.54 v2(36.42,41.43)
  BOTTOM w0.203: v2(36.42,41.43) 35.88,40.89 J5.23
TFT_DISP_DB10: length 42.3
  TOP w0.203: v2(37.26,41.35) 37.26,40.36 38.76,38.86 38.76,23.01 39.95,21.82 52.78,21.82 J2.6
  BOTTOM w0.203: J5.24 36.3,40.39 v2(37.26,41.35)
TFT_DISP_DB11: length 47.6
  TOP w0.203: v2(38.28,42.01) 39.85,40.44 39.85,24.84 42.37,22.33 57.35,22.33 J2.10
  BOTTOM w0.203: J5.25 36.56,39.89 38.28,41.61 v2(38.28,42.01)
TFT_DISP_DB12: length 51.5
  TOP w0.203: v2(38.96,42.57) 38.96,42.01 40.34,40.64 40.34,24.99 42.49,22.83 59.39,22.83 J2.12
  BOTTOM w0.203: v2(38.96,42.57) 38.96,41.66 36.7,39.39 J5.26
TFT_DISP_DB13: length 34.5
  TOP w0.203: J4.8 43.33,65 31.06,52.73 31.06,44.7 v2(30.76,44.4)
  BOTTOM w0.203: J5.27 31.22,38.89 30.76,39.34 v2(30.76,44.4)
TFT_DISP_DB14: length 33.3
  TOP w0.203: J3.1 30.61,54.51 30.61,45.24 29.74,44.37 v2(29.74,43.79)
  BOTTOM w0.203: v2(29.74,43.79) 29.74,39.57 30.93,38.39 J5.28
TFT_DISP_DB15: length 33.8
  TOP w0.203: J3.2 30.25,56.69 30.25,45.52 28.78,44.04 v2(28.78,43.13)
  BOTTOM w0.203: J5.29 30.46,37.89 28.78,39.57 v2(28.78,43.13)
TFT_DISP_RD_L: length 26.1
  TOP w0.203: J3.3 27.76,56.74 27.76,50.77 28.52,50.01 28.52,47.02 v2(28.93,46.61)
  BOTTOM w0.203: v2(28.93,46.61) 30.12,46.61 30.84,45.89 J5.13
TFT_DISP_RST_L: length 34.8
  TOP w0.203: J3.6 24.71,61.32 24.71,40.94 v2(26.7,38.96)
  BOTTOM w0.203: J5.30 30.07,37.39 28.5,38.96 v2(26.7,38.96)
TFT_DISP_WR_L: length 25.4
  TOP w0.203: v2(27.84,47.57) 27.89,47.62 27.89,49.76 27.2,50.44 27.2,58.72 J3.4
  BOTTOM w0.203: J5.12 31.11,46.39 29.92,47.57 v2(27.84,47.57)
VIO_REF: length 128
  TOP w0.254: v2(26.37,9.75) 26.37,9.76 26.11,10.02 U1.5 ; U1.8 v2(26.37,11.78) ; U1.12 24.21,11.02 v2(24.46,10.77)
  TOP w0.381: 29.92,16.74 30.79,17.61 ; 29.92,16.74 29.92,15.21 ; 29.92,16.74 29.05,15.87 ; 29.92,16.74 29.92,18.14 ; 29.92,16.74 29.05,17.61 ; 29.92,16.74 30.79,15.87
  TOP w0.635: v1(55.7,30.58) 65.61,30.58 70.43,25.76 v1(70.43,13.44) 70.43,5.05 v1(67.13,1.75)
  BOTTOM w0.203: U3.16 52.64,34.28 53.39,33.53 C15.1
  BOTTOM w0.279: C4.1 34.49,47.98 34.09,48.39 J5.8
  BOTTOM w0.381: 29.05,17.61 29.92,16.74 ; 29.92,16.74 30.79,17.61 ; 29.92,16.74 29.05,15.87 ; 29.92,16.74 30.79,15.87 ; 24.47,11.07 C30.1 ; C30.1 24.47,12.25 ; C30.1 25.05,11.66 ; 24.47,10.6 C32.1 25.05,10.01
  BOTTOM w0.635: C15.1 54.37,32.92 C20.1 55.56,30.72 v1(55.7,30.58) ; v1(38.68,47.99) v1(37.36,47.99) C3.1 36.45,47.98 C4.1 ; R20.2 v1(70.43,13.44) ; C32.1 24.47,5.7 TP9.1 24.59,0.99 66.37,0.99 v1(67.13,1.75)
N17262592: length 5.6
  BOTTOM w0.203: U3.9 53.31,37.08 53.54,37.31 54.55,37.31 R8.2
N17262616: length 5
  BOTTOM w0.203: U3.10 54.81,36.68 55.83,37.69 R10.2
N17313413: length 3.3
  BOTTOM w0.203: C7.2 51.11,40.63 U3.7
N17337588: length 3.3
  BOTTOM w0.203: R6.1 51.51,39.72 U3.8
N17337626: length 4.9
  BOTTOM w0.203: R16.2 56.39,34.2 53.23,34.2 52.75,34.68 U3.15
N17337628: length 7.9
  BOTTOM w0.203: R15.2 58.74,34.65 53.35,34.65 52.92,35.08 U3.14
N17337654: length 8.1
  BOTTOM w0.203: U3.11 53.31,36.28 53.42,36.17 55.32,36.17 55.96,36.8 58.61,36.8 R9.2
N17337656: length 4.8
  BOTTOM w0.203: U3.12 53.2,35.88 53.42,35.66 55.7,35.66 55.96,35.92 R14.2
N17337674: length 7.8
  BOTTOM w0.203: R13.2 58.74,35.15 53.42,35.15 53.09,35.48 U3.13
N17337833: length 3.7
  BOTTOM w0.203: C16.2 45.93,34.01 46.69,34.01 47.35,34.68 U3.26
N17337835: length 5.7
  BOTTOM w0.203: C16.1 44.64,34.52 46.43,34.52 46.99,35.08 U3.27
N17337935: length 5.2
  BOTTOM w0.203: C10.1 46.56,38.21 46.56,36.93 47.21,36.28 U3.30
N17337954: length 6.4
  BOTTOM w0.203: U3.31 47.44,36.68 47.07,37.06 47.07,39.36 C9.1
N17338534: length 4.9
  BOTTOM w0.203: U3.24 48.71,32.48 47.7,31.47 C21.1
N17339065: length 1.8
  BOTTOM w0.203: C24.1 43.63,28.93 R17.1
N17348097: length 16.5
  TOP w0.203: v2(66.88,46.96) 68.19,46.96 TP1.1
  BOTTOM w0.203: R5.1 57.41,44.27 C5.1 65.58,45.67 v2(66.88,46.96)
N173390790: length 1.5
  BOTTOM w0.203: R18.1 C26.1

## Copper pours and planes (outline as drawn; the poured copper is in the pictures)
AGND on TOP: 57.35,32.36 59,32.36 59.18,32.18 59.18,31.57 58.95,31.34 55.19,31.34 54.69,30.84 54.69,28.73 53.47,27.51 50.37,27.51 45.95,23.09 43.15,23.09 41.15,25.1 41.15,43.59 43.13,45.57 54.69,45.57 56.85,43.41 56.85,32.87
AGND on BOTTOM: 42.88,23.09 42.88,25.37 40.21,25.37 40.21,30.84 42.49,33.12 42.49,44.17 43.89,45.57 54.08,45.57 54.94,46.43 55.98,46.43 56.25,46.16 56.25,42.74 56.85,42.14 56.85,39.98 57.1,39.73 57.1,38.2 56.85,37.95 56.85,33.63 57.61,32.87 58.88,32.87 59.39,32.36 59.39,31.47 59.26,31.34 55.32,31.34 54.81,30.84 54.81,29.82 54.69,29.69 54.69,29.18 53.11,27.61 48.67,27.61 48.56,27.51 48.56,27.46 47.6,26.49 47.57,26.49 47.57,24.99 45.67,23.09 ; 4 cut-outs
VCC_3V3 on TOP: 36.02,21.06 36.4,20.68 36.4,15.34 35.76,14.71 33.55,14.71 33.1,15.16 33.1,17.63 32.16,18.57 32.16,37.01 33.38,38.23 35.64,38.23 36.02,37.85
VCC_3V3 on BOTTOM: 33.73,37.57 33.73,14.2 36.53,11.4 45.03,11.4 47.32,13.69 47.32,19.66 51.13,23.47 56.72,23.47 69.67,36.42 69.67,52.3 68.91,53.06 37.92,53.06 36.02,51.16 36.02,39.85 ; 2 cut-outs
VIO_REF on TOP: 31.46,39.36 31.46,39.34 30.94,38.82 30.94,19.58 31.45,19.08 31.45,15.52 30.89,14.96 29.06,14.96 28.57,15.44 28.57,39.14 36.65,47.22 36.65,48.09 37.08,48.53 38.79,48.53 39.19,48.12 39.19,47.09
VIO_REF on BOTTOM: 31.32,14.96 31.32,18.39 30.81,18.9 24.69,18.9 24.08,18.29 24.08,9.12 26.75,9.12 26.75,13.31 27.76,14.33 30.68,14.33

Small or netless copper shapes (teardrops, artwork), in the pictures only: 1 on TOP, 1 on BOTTOM

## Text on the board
BOTTOM: BOTTOM
Ref Des/Assembly Bottom: 1 | / ASSEMBLY BOTTOM
Board Geometry/Soldermask Bottom: SOLDER MASK BOTTOM
Ref Des/Silkscreen Bottom: 1 | AHJ | OMTP | SILK SCREEN BOTTOM
TOP: TOP
Ref Des/Assembly Top: / ASSEMBLY TOP
Board Geometry/Soldermask Top: SOLDER MASK TOP
Ref Des/Silkscreen Top: VIO_REF | V3.3 | PDM MIC | DVDD_1V8 | MIC BIAS | RIN3 | LIN2 | LOUT | ROUT | RIN2 | LIN3 | SCL | SDA | NC | GND | DISP_RST | DISP_D/C | DISP_WR | DISP_RD | DB15 | DB14 | DB13 | RX_SDI | RX_WS | DB8 | ALS_OUT | RX_SCK | DB9 | CODEC_PDN | TX_SDO | DB10 | IMU_INT1 | TX_WS | IMU_INT2 | TX_SCK | DB11 | PDM_CLK | MCLK | DB12 | PDM_DATA | J3 | MOTION | SENSOR | J1 | LIGHT SENSOR | AMBIENT | 1 | J4 | J2 | TFT DISPLAY SHIELD | SILK SCREEN TOP
PAGE_OUTLINE: SOLDER PASTE TOP
DIMENSION: (6 PLACE) | SOLDER PASTE BOTTOM
User.15: 1 | GND | 2 | 16 | 9 | A12 | A1 | 3 | 4 | CURRENT | SENSE | P | RST | . | NC | 0 | 5 | 10 | N | VDD SEL | A | R | 11 | G | B | 42 | 21 | (1.0) | TX | R3 | R7 | C11 | C15 | R14 | R16 | R5 | R2 | J3 | J7 | R15 | C36 | R12 | R200 | R19 | C5 | R21 | R22 | TP9 | TP4 | TP5 | TP8 | TP10 | TP11 | TP13 | R23 | C10 | R24 | R25 | 15 | P6VDD | 12 | SLD0(8.3) | SLD1(8.4) | SLD2(8.5) | SLD3(8.6) | SLD4(8.7) | C120 | R20 | USB PD OUT | B1 | B12 | BAT CHARG | KITPROG2 | P5LP | SWD | VDD | PSoC 5LP I/Os | VIN | PD OUT | 6 | I | C | 7 | O | L | J15 | K | USB | 0.4 | KITPROG2 STATUS | CYPD3125 | P5LP1.2 | P5LP15.0 | 20 | POWER | VCC.5V | 40 | LED | - | 40LQXIES | PSoC 6 PIONEER KIT | 8 | CY8CKIT-062 | CY8C5868LTI-LP039 | PMOD | 51 | 68 | 17 | MB39C022 | P6.VDD | P6 DEBUG & TRACE | VBAT | BAT_TS | VCC.3V3 | VDD_NS | VRF | 19 | P6 PROG | 13 | CY8C6237BZI- | 1.8V-3.3V | VARIABLE | 1.8V | 3.3V | BLD74 | 8.0 | PROXIMITY | U6 | BTN0 | F-RAM.VDD | (8.1) | RX0 | SLIDER | S25FL512SAGBHIA10 | (8.2) | RX1 | VDDA | BTN1 | VDDD | J13 | J11 | J17 | J22 | J4 | LED2 | R26 | C101 | C8 | LED1 | J2 | J6 | SW2 | R28 | U2 | R47 | R29 | SW3 | LED7 | LED4 | LED5 | LED6 | R48 | J16 | J18 | R49 | R50 | C38 | R39 | C31 | C33 | R38 | R8 | J23 | R6 | R1 | U29 | U7 | U30 | C29 | SW5 | R32 | D2 | R9 | R33 | D1 | R31 | C14 | R35 | R4 | C9 | R10 | R208 | U8 | C41 | C42 | C40 | R43 | J21 | J20 | C121 | J12 | C133 | U9 | L7 | C32 | C27 | U3 | C28 | C30 | SW1 | R27 | R30 | R34 | R40 | J9 | R56 | J19 | C39 | C34 | R41 | R42 | R46 | R51 | R52 | R53 | R54 | R55 | C37 | C16 | R57 | C35 | C18 | C24 | L6 | L4 | C19 | C25 | R36 | R37 | L5 | C20 | C26 | C17 | R17 | J1 | U4 | R13 | R18 | R11 | U5 | LED3 | E | U1 | C6 | C3 | C4 | LED8 | J8 | IN | LED9 | C2 | R203 | L1 | L2 | C12 | C7 | ANT1 | C1 | L3 | C13 | ( | SCL | SDA | F | V | D | D9 | D8 | D7 | D6 | ) | A0 | D5 | D4 | D3 | A2 | A3 | A4 | A5 | D0 | C155 | R44 | R45 | J10 | C21 | C22 | C23 | R201 | R202 | J5
User.19: A. IMPEDANCE MATCHING NOT REQUIRED
User.23: TFT DISPLAY SHIELD
User.24: 2
User.45: FIGURE | SIZE | 9.84 | 10.0 | 40.16 | 45.28 | 66.93 | DRILL CHART: TOP to BOTTOM | ALL UNITS ARE IN MILS | TOLERANCE | +1.97/-9.84 | +3.0/-10.0 | +3.0/-3.0 | +1.97/-1.97 | PLATED | NON-PLATED | QTY | 68 | 238 | 16 | 26 | 2
